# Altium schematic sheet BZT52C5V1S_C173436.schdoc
size 127 x 101 mm
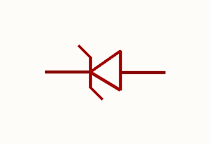
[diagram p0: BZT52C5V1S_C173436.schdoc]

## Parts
D?  bzt52c5v1s_c173436  [SOD-323_L1.8-W1.3-LS2.5-RD]  (value not drawn)

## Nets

Not connected (* = marked no-connect by the designer): D? 1 2

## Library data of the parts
D? = bzt52c5v1s_c173436: 二极管配置:1个独立式;稳压值(标称值):5.1V;稳压值(范围):4.8V~5.4V;耗散功率(Pd):200mW;; Manufacturer: MDD(辰达半导体); AddInBom: yes; ModelId: db63db13d9e342eb939127d413d6200b; ModelTransform: 104.3305,51.181,0,0,0,0,0,-0.004,0; Diode Configuration: 1个独立式; Zener Voltage(Nom): 5.1V; Reverse Leakage Current (Ir): 2uA@1.5V; Pd - Power Dissipation: 200mW; Impedance(Zzt): 130Ω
